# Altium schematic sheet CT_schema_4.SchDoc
size 395 x 205 mm
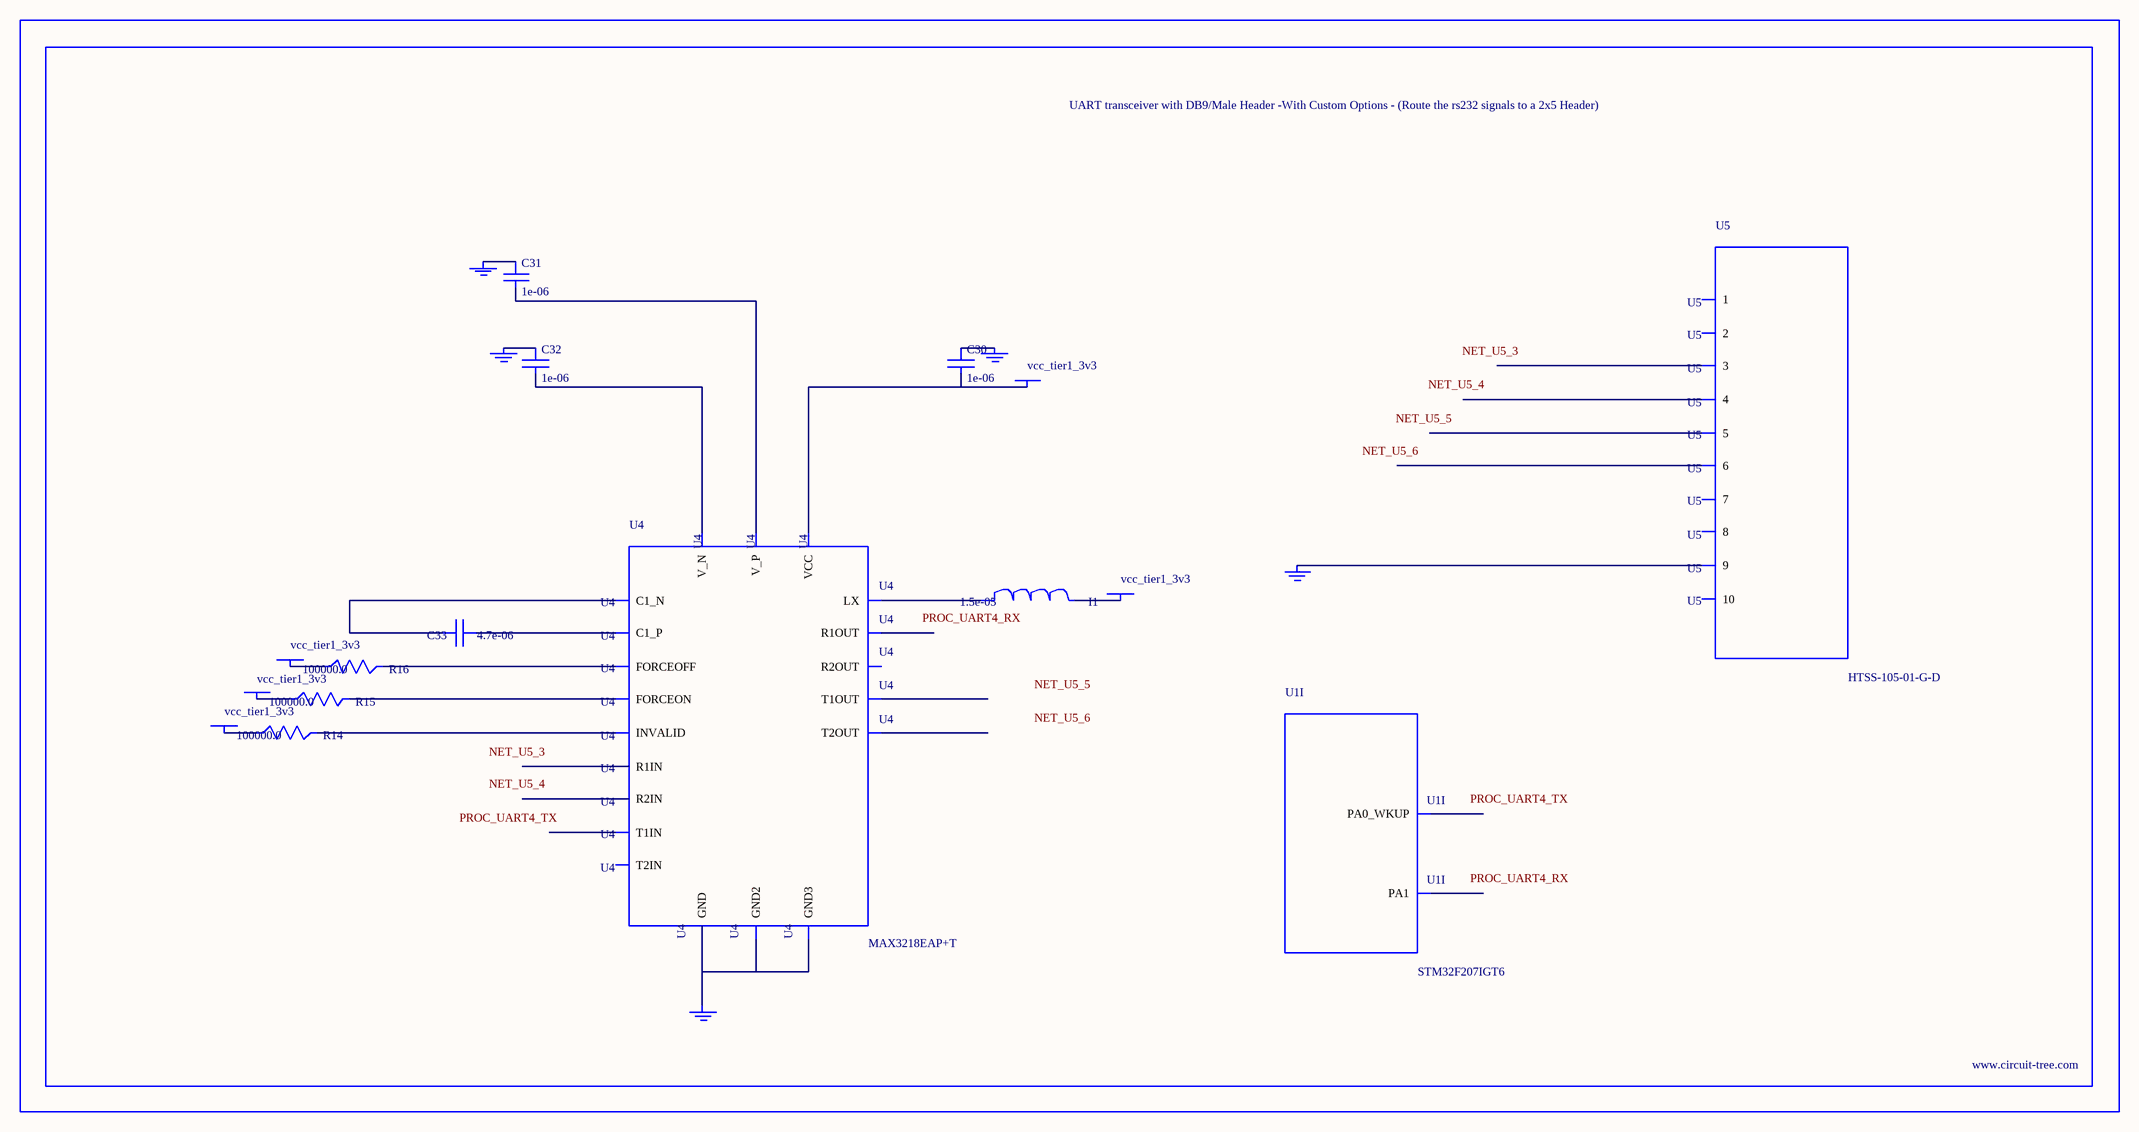
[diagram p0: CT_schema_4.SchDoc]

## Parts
BORDER3  (no value)
C30  1e-06  [C0603]
C31  1e-06  [C0603]
C32  1e-06  [C0603]
C33  4.7e-06  [C0805]
GND_INSTANCE_3_0  (no value)
GND_INSTANCE_3_1  (no value)
GND_INSTANCE_3_2  (no value)
GND_INSTANCE_3_3  (no value)
GND_INSTANCE_3_4  (no value)
I1  1.5e-05  [L1210]
POWER_INSTANCE_3_0  vcc_tier1_3v3
POWER_INSTANCE_3_1  vcc_tier1_3v3
POWER_INSTANCE_3_2  vcc_tier1_3v3
POWER_INSTANCE_3_3  vcc_tier1_3v3
POWER_INSTANCE_3_4  vcc_tier1_3v3
R14  100000.0  [R0603]
R15  100000.0  [R0603]
R16  100000.0  [R0603]
U1  STM32F207IGT6  [LQFP176]  (part I of 15)
U4  MAX3218EAP+T  [SSOP-20]
U5  HTSS-105-01-G-D  [HTSS-105-01-G-D]

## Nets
NetC30_1: C30.1 GND_INSTANCE_3_0.0(GND)
NetC30_2: C30.2 POWER_INSTANCE_3_4.0(PWR) U4.6(VCC)
NetC31_1: C31.1 GND_INSTANCE_3_2.0(GND)
NetC31_2: C31.2 U4.19(V_P)
NetC32_1: C32.1 GND_INSTANCE_3_1.0(GND)
NetC32_2: C32.2 U4.15(V_N)
NetC33_1: C33.1 U4.18(C1_P)
NetC33_2: C33.2 U4.16(C1_N)
NetGND_INSTANCE_3_3_0: GND_INSTANCE_3_3.0(GND) U4.5(GND) U4.17(GND2) U4.20(GND3)
NetGND_INSTANCE_3_4_0: GND_INSTANCE_3_4.0(GND) U5.9
NetI1_1: I1.1 U4.1(LX)
NetI1_2: I1.2 POWER_INSTANCE_3_0.0(PWR)
NetPOWER_INSTANCE_3_1_0: POWER_INSTANCE_3_1.0(PWR) R14.1
NetPOWER_INSTANCE_3_2_0: POWER_INSTANCE_3_2.0(PWR) R15.1
NetPOWER_INSTANCE_3_3_0: POWER_INSTANCE_3_3.0(PWR) R16.1
NetR14_2: R14.2 U4.2(INVALID)
NetR15_2: R15.2 U4.3(FORCEON)
NetR16_2: R16.2 U4.4(FORCEOFF)

Not connected (* = marked no-connect by the designer): U1 40(PA0_WKUP) 41(PA1); U4 7(T1IN) 8(T2IN) 9(R1OUT) 10(R2OUT) 11(R2IN) 12(R1IN) 13(T2OUT) 14(T1OUT); U5 1 2 3 4 5 6 7 8 10

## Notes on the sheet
- Labels drawn without touching a wire or pin: NET_U5_3, NET_U5_4, NET_U5_5, NET_U5_6, PROC_UART4_RX, PROC_UART4_TX

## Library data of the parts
BORDER3 = BORDER_PAGE3
C30-C32 = C0603C105K3RACTU
C33 = C0805C475K4RACTU
GND_INSTANCE_3_0-GND_INSTANCE_3_4 = GND
I1 = L1210R150MDWIT
POWER_INSTANCE_3_0-POWER_INSTANCE_3_4 = PWR
R14-R16 = RC0603JR-07100KL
